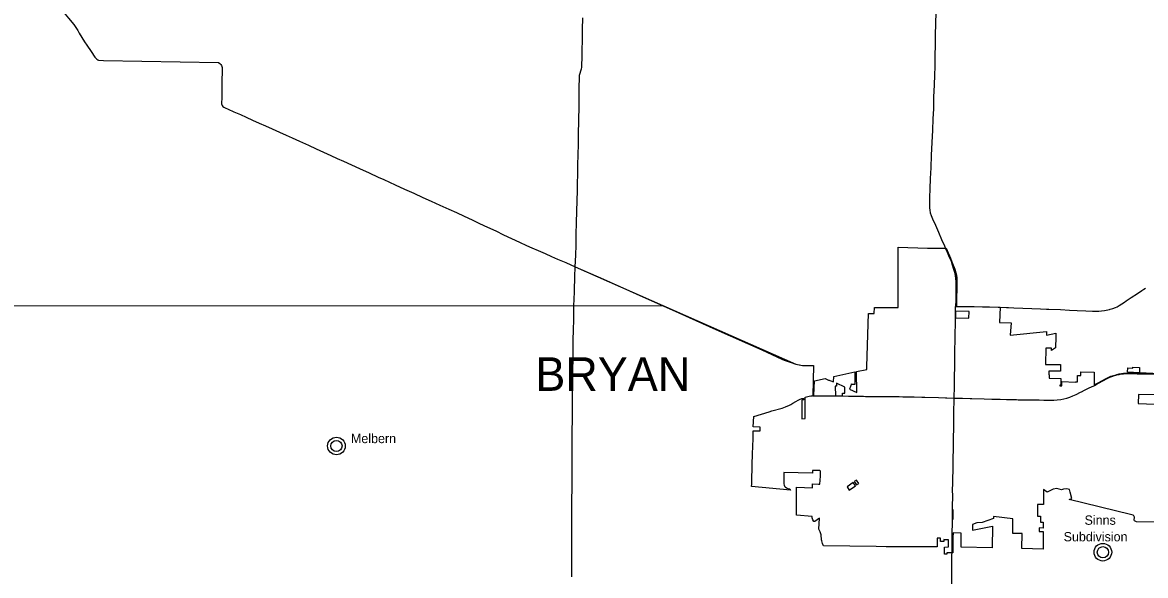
# Model space of a CAD drawing. Extents: x -66 to 795, y 0 to 440.
# Drawn here: x 240.8 to 383.6, y 105 to 175.4 of the extents above; entities that cross this region are included whole.
import ezdxf

# ---------------------------------------------------------------- set-up
doc = ezdxf.new("R2010")
doc.units = 0
for name, color, linetype in [('DV_X_Corp_Line', 7, 'Continuous'), ('GM_X_Corporation_Text', 7, 'Continuous'), ('GM_X_State_Route', 7, 'Continuous'), ('GM_X_US_Route', 7, 'Continuous'), ('RD_P_Fence', 7, 'Continuous'), ('SH_Data', 7, 'Continuous')]:
    doc.layers.add(name, color=color, linetype=linetype)

msp = doc.modelspace()

# ---------------------------------------------------------------- linework, layer by layer
at = {"layer": 'DV_X_Corp_Line'}
for points in [[(385.94, 111.78), (382.44, 111.85), (382.28, 111.9), (382.21, 111.97), (382.17, 112.05), (382.18, 112.45), (382.12, 112.61), (382.02, 112.68), (381.71, 112.77), (373.88, 114.67), (374.22, 114.81), (374.01, 115.6), (373.92, 115.97), (373.6, 116.05), (373.16, 115.99), (372.93, 115.91), (372.34, 116.08), (371.86, 116), (371.12, 115.59), (370.65, 115.96), (370.63, 114.04), (369.89, 114.06), (369.87, 112.56), (370.25, 112.55), (370.24, 111.8), (370.61, 111.79), (370.6, 111.04), (370.1, 111.06), (370.1, 110.6), (370.59, 110.59), (370.57, 108.37), (367.86, 108.43), (367.91, 110.33), (366.72, 110.37), (366.73, 112.22), (364.28, 112.51), (364.27, 112.24), (362.84, 111.77), (362.14, 111.71), (361.62, 111.5), (361.62, 110.77), (364.14, 111.27), (364.11, 108.52), (360.15, 108.59), (360.16, 110.39), (359.13, 110.43), (359.12, 109.88), (359.11, 108.62), (359.1, 107.87), (358.34, 107.89), (358.33, 107.72), (358.04, 107.72), (358.04, 108.62), (358.54, 108.64), (358.54, 109.55), (358.04, 109.56), (357.95, 109.57), (357.96, 109.32), (357.53, 109.32), (357.53, 109.76), (357.1, 109.76), (357.12, 108.66), (354.32, 108.67), (353.73, 108.67), (350.65, 108.67), (349.36, 108.68), (342.66, 108.78), (342.54, 109.07), (342.44, 109.41), (342.42, 109.53), (342.36, 110.19), (342.26, 110.56), (342.08, 110.91), (342.14, 112.29), (341.55, 111.87), (341.46, 111.86), (341.32, 112.1), (341.27, 112.22), (341.24, 112.36), (341.21, 112.5), (339.23, 112.7), (339.23, 116.23), (341.25, 116.16), (341.26, 116.65), (342.03, 116.61), (342.19, 116.61), (342.29, 117.66), (342.29, 118.28), (342.18, 118.36), (341.28, 118.36), (341.27, 118.02), (337.64, 118.1), (337.64, 116.98), (337.64, 116.68), (337.67, 116.5), (337.7, 116.39), (337.78, 116.31), (337.81, 116.28), (337.96, 116.15), (338.05, 116.1), (338.14, 116.07), (338.22, 116.05), (338.27, 116.04), (338.33, 116.03), (338.38, 115.99), (338.42, 115.94), (338.46, 115.87), (333.53, 116.34), (333.54, 116.64), (333.62, 119.4), (333.64, 120.19), (333.69, 121.73), (333.71, 122.16), (333.74, 123.42), (334.61, 123.43), (334.61, 123.87), (333.75, 123.91), (333.8, 125.26), (335.76, 125.85), (336.11, 125.95), (337.42, 126.32), (337.83, 126.46), (338.35, 126.69), (338.51, 126.78), (338.77, 126.92), (339.15, 127.14), (339.43, 127.3), (339.6, 127.39), (339.92, 127.53), (340.17, 127.55), (340.19, 127.34), (339.92, 127.32), (339.92, 124.96), (340.34, 124.98), (340.34, 125.28), (340.33, 125.82), (340.33, 127.69), (340.68, 127.78), (340.85, 127.83), (341.06, 127.87), (341.24, 127.89), (341.45, 127.91), (341.52, 129.77), (342.87, 130.07), (343.21, 129.9), (343.31, 129.84), (343.35, 129.86), (343.39, 129.86), (343.48, 129.83), (343.92, 129.64), (343.98, 130.34), (346.67, 130.92), (346.67, 129.32), (346.24, 129.32), (346.24, 129.38), (345.96, 128.73), (346.91, 128.3), (346.86, 130.96), (348.17, 131.24), (348.17, 131.59), (348.37, 138.36), (349.12, 138.35), (349.14, 139.13), (350.17, 139.13), (351.3, 139.12), (351.84, 139.12), (352.16, 139.12), (352.18, 146.78), (355.89, 146.68), (358.24, 146.65), (358.8, 145.37), (359.08, 144.73), (359.38, 143.98), (359.46, 143.71), (359.51, 143.53), (359.57, 143.21), (359.59, 143.1), (359.6, 142.99), (359.61, 142.85), (359.62, 142.73), (359.62, 142.06), (359.6, 141.19), (359.58, 140.58), (359.57, 139.25), (360.66, 139.23), (365.11, 139.17), (365.06, 137.19), (366.52, 137.18), (366.4, 135.6), (371.02, 136.07), (371.02, 135.59), (372.22, 135.84), (372.21, 135.37), (372.15, 133.97), (371.63, 133.62), (371.64, 133.94), (370.95, 133.95), (370.93, 133.52), (370.91, 133.1), (370.9, 132.76), (370.88, 131.86), (372.8, 131.86), (372.8, 131), (371.3, 131.03), (371.29, 130.54), (371.35, 130.54), (371.34, 130.11), (372.84, 130.07), (372.82, 129.21), (372.7, 129.21), (372.7, 129.14), (372.98, 129.13), (372.98, 129.69), (374.7, 129.61), (374.7, 129.65), (374.96, 129.65), (374.97, 130.46), (375.36, 130.46), (375.36, 130.93), (377.08, 130.89), (377.07, 129.25), (377.57, 129.52), (378.52, 130.02), (378.94, 130.23), (379.2, 130.36), (379.53, 130.46), (379.73, 130.52), (379.95, 130.58), (380.23, 130.65), (380.54, 130.7), (380.81, 130.74), (381.18, 130.77), (382.14, 130.76), (382.85, 130.75), (382.85, 130.78), (381.33, 130.87), (381.36, 131.45), (381.98, 131.4), (381.99, 131.52), (382.83, 131.49), (382.85, 130.82), (385.37, 130.7)], [(386.76, 127.99), (382.72, 128.02), (382.68, 126.88), (384.8, 126.82)]]:
    msp.add_lwpolyline(points, dxfattribs=at)
for points in [[(359.44, 137.81), (361.13, 137.77), (361.2, 138.62), (359.45, 138.66)], [(344.14, 129.08), (344.21, 127.86), (345.09, 127.85), (345.09, 128.21), (345.38, 128.21), (345.39, 128.97), (344.32, 129.49), (344.32, 129.08)], [(346.86, 117.15), (346.58, 116.95), (346.79, 116.65), (346.88, 116.53), (347.16, 116.73)], [(345.95, 115.86), (346.73, 116.42), (346.43, 116.84), (345.66, 116.28)], [(359.05, 112.18), (359.15, 112.18), (359.15, 113.38), (359.06, 113.38)]]:
    msp.add_lwpolyline(points, close=True, dxfattribs=at)
for centre, radius in [((280.76, 121.49), 1.12), ((280.76, 121.49), 0.71), ((378.18, 107.97), 1.12), ((378.18, 107.97), 0.71)]:
    msp.add_circle(centre, radius, dxfattribs=at)
at = {"layer": 'GM_X_State_Route'}
for points in [[(241.15, 178.25), (241.15, 178.25), (242.23, 178.23), (243.11, 178.22), (243.64, 178.2), (243.83, 178.19), (244.12, 178.14), (244.41, 178.05), (244.69, 177.95), (244.9, 177.85), (245, 177.78), (245.58, 177.24), (246.28, 176.44), (246.72, 175.94), (247.38, 175.13), (247.56, 174.87), (247.87, 174.36), (247.88, 174.35)], [(311.57, 163.02), (311.57, 163.19), (311.6, 164.45), (311.62, 165.96), (311.63, 167.14), (311.64, 168.28), (311.67, 168.66), (311.69, 168.8), (311.73, 168.94), (311.83, 169.23), (311.91, 169.48), (311.94, 169.64), (311.96, 169.79), (311.97, 170.06), (311.99, 170.82), (312.01, 171.86), (312.03, 173.15), (312.05, 174.5), (312.08, 175.98)], [(356.94, 176.64), (356.91, 175.25), (356.88, 173.78), (356.85, 172.51), (356.83, 171.19), (356.81, 169.77), (356.77, 168.68), (356.74, 167.45), (356.67, 165.86), (356.63, 164.39), (356.57, 163.11), (356.52, 161.69), (356.45, 160.12), (356.37, 158.48), (356.31, 156.9), (356.24, 155.55), (356.2, 154.21)], [(247.88, 174.35), (247.88, 174.35), (248.07, 174.02), (248.74, 172.94), (249.05, 172.49), (249.57, 171.71), (250.05, 170.99), (250.2, 170.81), (250.31, 170.71), (250.41, 170.63), (250.53, 170.57), (251.13, 170.56)], [(251.13, 170.56), (265.77, 170.28), (265.93, 170.18), (266.05, 170.05), (266.14, 169.93), (266.21, 169.79), (266.22, 169.65), (266.22, 169.04), (266.21, 168.14), (266.2, 167.06), (266.18, 165.89), (266.17, 165.05), (266.19, 164.92), (266.22, 164.84), (266.33, 164.7), (266.45, 164.61), (266.63, 164.51), (267, 164.35), (267.73, 164.02), (268.55, 163.66), (269.29, 163.32), (270.08, 162.97), (270.92, 162.59), (271.75, 162.22), (272.59, 161.84), (273.53, 161.42), (274.37, 161.05), (275.14, 160.7), (276.08, 160.27), (277.2, 159.76), (278.18, 159.32), (279.11, 158.89), (280.05, 158.47), (280.86, 158.09), (281.65, 157.72), (282.69, 157.26), (283.7, 156.79), (284.91, 156.25), (286.07, 155.72), (286.77, 155.39), (288.23, 154.72), (289.43, 154.19), (290.6, 153.66), (291.75, 153.13), (292.81, 152.65), (293.91, 152.15), (295.05, 151.63), (296.01, 151.2), (297.01, 150.73), (298, 150.26), (298.96, 149.81), (299.94, 149.35), (301.01, 148.85), (302.01, 148.37), (303.02, 147.9), (304.01, 147.43), (304.9, 147.02), (305.61, 146.69), (306.41, 146.35), (307.27, 145.97), (308.11, 145.6), (308.85, 145.28), (309.9, 144.82), (311.09, 144.28)], [(311.46, 157.43), (311.48, 158.39), (311.51, 160.07), (311.54, 161.31), (311.56, 162.78), (311.57, 163.02)], [(311.4, 154.25), (311.4, 154.56), (311.4, 154.71), (311.42, 155.14), (311.43, 155.83), (311.45, 156.97), (311.45, 157.25), (311.46, 157.43)], [(311.09, 144.28), (311.17, 145.76), (311.22, 147.06), (311.25, 148.42), (311.29, 149.92), (311.32, 151.34), (311.36, 152.71), (311.39, 153.96), (311.39, 153.97), (311.4, 154.25)], [(356.2, 154.21), (356.19, 154.09), (356.15, 153.25), (356.13, 152.38), (356.13, 152.07), (356.13, 151.8), (356.18, 151.5), (356.24, 151.18), (356.36, 150.8), (356.51, 150.41), (356.89, 149.59), (357.27, 148.68), (357.68, 147.75), (358.04, 146.94), (358.19, 146.6)], [(358.19, 146.6), (358.37, 146.17), (358.66, 145.5), (358.89, 144.99), (359.04, 144.55), (359.2, 144.01), (359.3, 143.61), (359.39, 143.2), (359.46, 142.79), (359.48, 142.43)], [(310.75, 127.36), (310.77, 128.62), (310.79, 130), (310.82, 131.28), (310.83, 132.49), (310.85, 133.73), (310.87, 134.99), (310.9, 136.24), (310.92, 137.57), (310.94, 138.91), (310.95, 139.48), (310.96, 140), (311.01, 141.29), (311.07, 143.01), (311.09, 144.28)], [(311.09, 144.28), (314.71, 142.71), (318.86, 140.85), (324.3, 138.45), (326.44, 137.47), (328.99, 136.31), (334.83, 133.74), (337.37, 132.55), (337.68, 132.43)], [(359.48, 141.83), (359.48, 141.52), (359.48, 141.03), (359.47, 140.05), (359.46, 139.25)], [(359.48, 142.43), (359.48, 142.38), (359.48, 141.85), (359.48, 141.83)], [(337.68, 132.43), (337.69, 132.43), (338.43, 132.16), (339.16, 131.89), (339.63, 131.8), (339.99, 131.73), (340.52, 131.73)], [(340.52, 131.73), (341.41, 131.72), (341.33, 127.89), (341.64, 127.89), (341.64, 127.89)], [(377.1, 129.2), (377.46, 129.38), (377.63, 129.47), (378.26, 129.82), (378.74, 130.08), (379.07, 130.24), (379.34, 130.34), (379.64, 130.44), (379.83, 130.49), (379.95, 130.53), (380.23, 130.6), (380.51, 130.65), (380.81, 130.67), (381.14, 130.7), (381.31, 130.7)], [(381.31, 130.7), (381.44, 130.71), (381.89, 130.7), (382.09, 130.7), (382.21, 130.7)], [(382.21, 130.7), (382.55, 130.69), (382.66, 130.69), (382.81, 130.69)], [(382.81, 130.69), (383.12, 130.68)], [(383.12, 130.68), (383.14, 130.68), (383.89, 130.67), (384.57, 130.66), (384.68, 130.65)], [(375.47, 128.39), (375.86, 128.59), (376.45, 128.88), (377.03, 129.16), (377.1, 129.2), (377.1, 129.2)], [(310.75, 125.54), (310.75, 127.07), (310.75, 127.36)], [(341.64, 127.89), (342.4, 127.88)], [(342.4, 127.88), (342.61, 127.88), (343.22, 127.87), (343.77, 127.86), (344.03, 127.86), (344.77, 127.85), (345.85, 127.84), (346.51, 127.83), (346.53, 127.83)], [(346.53, 127.83), (346.53, 127.83), (346.95, 127.83), (347.51, 127.81), (347.75, 127.81), (348, 127.8), (348.5, 127.8), (349.12, 127.79), (349.41, 127.79), (349.93, 127.78), (350.24, 127.78), (350.84, 127.77), (351.68, 127.77), (351.78, 127.77), (352.03, 127.77), (352.29, 127.77), (352.77, 127.76), (353.22, 127.76), (353.48, 127.75)], [(353.48, 127.75), (354.18, 127.74), (354.2, 127.74), (354.21, 127.74)], [(354.21, 127.74), (354.21, 127.74), (355.15, 127.72), (355.53, 127.71), (357.28, 127.66), (357.29, 127.66)], [(357.29, 127.66), (358.17, 127.62), (358.33, 127.62), (358.33, 127.62)], [(358.33, 127.62), (359.28, 127.59)], [(359.28, 127.59), (360.33, 127.56)], [(360.33, 127.56), (360.34, 127.56), (361.32, 127.53), (361.53, 127.53)], [(361.53, 127.53), (363.08, 127.49), (364.08, 127.45), (365.13, 127.43), (365.94, 127.41), (367.22, 127.39)], [(367.22, 127.39), (367.43, 127.38), (368.54, 127.36), (369.31, 127.35), (369.57, 127.34), (370.07, 127.34)], [(370.07, 127.34), (370.07, 127.34), (370.67, 127.33)], [(370.67, 127.33), (371.38, 127.32), (371.95, 127.32), (372.39, 127.35), (372.83, 127.4), (373.21, 127.47), (373.62, 127.58), (373.99, 127.71), (374.37, 127.85), (374.79, 128.05)], [(374.79, 128.05), (374.8, 128.05), (375.35, 128.33), (375.47, 128.39), (375.47, 128.39)], [(310.74, 122.23), (310.74, 123.27), (310.75, 124.94), (310.75, 125.54)], [(310.73, 120.9), (310.73, 121.15), (310.73, 121.87), (310.74, 122.23)], [(310.68, 104.82), (310.69, 106.4), (310.68, 108.07), (310.68, 109.16), (310.68, 109.36), (310.7, 111.04), (310.7, 112.9), (310.7, 114.49), (310.71, 116.24), (310.72, 118.05), (310.72, 118.69), (310.73, 119.69), (310.73, 119.86), (310.73, 120.9)]]:
    msp.add_lwpolyline(points, dxfattribs=at)
at = {"layer": 'GM_X_US_Route'}
for points in [[(381.14, 139.95), (381.79, 140.37), (382.57, 140.89), (383.14, 141.27), (383.26, 141.36), (383.37, 141.43)], [(383.37, 141.43), (383.6, 141.57)], [(359.46, 139.25), (360.66, 139.23), (361.84, 139.22), (362.88, 139.21), (363.79, 139.19), (364.88, 139.15), (365.94, 139.11), (366.18, 139.1), (366.87, 139.08), (367.99, 139.03), (369.13, 138.99), (370.25, 138.95), (371.02, 138.92), (371.31, 138.91), (372.78, 138.84), (373.95, 138.79), (374.93, 138.75), (376, 138.7), (376.88, 138.65), (377.43, 138.63), (377.67, 138.65), (377.99, 138.67), (378.4, 138.73), (378.79, 138.8), (379.01, 138.86), (379.1, 138.88), (379.46, 139), (379.77, 139.11), (380.01, 139.21), (380.27, 139.38), (380.92, 139.8), (381.13, 139.94), (381.14, 139.95)], [(359.44, 137.75), (359.45, 138.32), (359.45, 138.49), (359.45, 138.65)], [(359.45, 138.65), (359.46, 139.1)], [(359.46, 139.1), (359.46, 139.25)], [(359.43, 137), (359.43, 137.21), (359.44, 137.58), (359.44, 137.73), (359.44, 137.75)], [(359.41, 135.36), (359.41, 135.44), (359.42, 136.15), (359.42, 136.21), (359.43, 136.56)], [(359.43, 136.56), (359.43, 136.61), (359.43, 137)], [(359.33, 130.26), (359.35, 131.65), (359.36, 132.25), (359.37, 132.87), (359.38, 133.99), (359.38, 134.22), (359.39, 134.41), (359.4, 134.98), (359.4, 135.22), (359.41, 135.36)], [(359.28, 127.72), (359.31, 128.97), (359.33, 130.11), (359.33, 130.13), (359.33, 130.26)], [(359.23, 123.68), (359.23, 123.9), (359.25, 124.87), (359.25, 126.13), (359.25, 126.23), (359.27, 126.96), (359.28, 127.59), (359.28, 127.72)], [(359.2, 122.38), (359.2, 122.38), (359.21, 122.62), (359.23, 123.68)], [(359.1, 116.62), (359.12, 117.37), (359.13, 118.39), (359.14, 118.54), (359.14, 118.58), (359.16, 119.83), (359.17, 119.94), (359.18, 121.08), (359.19, 121.39), (359.2, 122.38)], [(359.06, 113.42), (359.07, 113.88), (359.09, 115), (359.08, 116), (359.1, 116.62)], [(359.05, 112.2), (359.05, 112.2), (359.05, 112.82), (359.06, 113.42), (359.06, 113.42)], [(359.03, 110.53), (359.03, 110.53), (359.04, 110.69), (359.05, 111.43), (359.05, 111.75)], [(359.05, 111.75), (359.05, 112.2)], [(359.03, 110.23), (359.03, 110.23), (359.03, 110.53)], [(359.03, 109.77), (359.03, 110.15), (359.03, 110.23)], [(359.01, 108.52), (359.02, 108.81), (359.03, 109.77)], [(359.01, 108.37), (359.01, 108.37), (359.01, 108.52)], [(358.96, 102.97), (358.97, 103.54), (358.99, 105.1), (358.99, 106.44), (359, 107.65), (359.01, 107.92)], [(359.01, 107.92), (359.01, 108.22), (359.01, 108.37)]]:
    msp.add_lwpolyline(points, dxfattribs=at)
at = {"layer": 'RD_P_Fence'}
msp.add_lwpolyline([(311.09, 144.28), (339.16, 131.89), (339.99, 131.73), (341.41, 131.72)], dxfattribs=at)
at = {"layer": 'SH_Data'}
msp.add_line((153.94, 139.28), (322.26, 139.35), dxfattribs=at)

# ---------------------------------------------------------------- texts
at = {"layer": 'DV_X_Corp_Line'}
for s, height, p in [('Melbern', 1.188, (282.6, 121.85)), ('Sinns', 1.188, (375.85, 111.46)), ('Subdivision', 1.1875, (373.19, 109.35))]:
    msp.add_text(s, height=height, rotation=0, dxfattribs=at).set_placement(p)
at = {"layer": 'GM_X_Corporation_Text'}
msp.add_text('BRYAN', height=4.275, rotation=0, dxfattribs=at).set_placement((306.04, 128.5))

doc.saveas('drawing.dxf')
